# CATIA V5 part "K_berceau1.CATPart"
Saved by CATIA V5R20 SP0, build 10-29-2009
Part number: berceau1
Bounding box of the stored display mesh (mm): x -13.994 to 13.994, y 95 to 105, z -10 to 63.99
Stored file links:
  G:\Khaled_CFAO_2011\SIL\SIL_GR2\mdupuis\Khaled\CAD_ThinkMOTION\K_berceau1.CATPart
  G:\Dupuis_Maxime_Thinkmotion_CFAO\assemblage.CATProduct
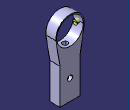
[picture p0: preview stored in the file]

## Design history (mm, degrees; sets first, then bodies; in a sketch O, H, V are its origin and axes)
External parameters (linked from other documents)
  External.diametrelunette = 20 mm
Set1
  Plane1 to Plane3: linked copy from another document
  Point1: linked copy from another document
  Line1: linked copy from another document
  Point2: linked copy from another document
Body1 (main body)
  Sketch1 on Plane3, origin (0, 100, 0), H (-1, 0, 0), V (0, 0, 1)
    point P1 (10, -10)
    line L1 (10, -10) -> (10, 25)
    point P2 (10, 25)
    line L2 (10, 25) -> (13.9237, 48.5401)
    point P3 (13.9237, 48.5401)
    point P4 (0, 50)
    line L3 (10, -10) -> (0, -10)
    point P5 (0, -10)
    reference projected point E1 (0, 50) from Point1
    point P6 (0, 36)
    reference intersected line E2 through (0, 0) direction (0, -1) from Plane2
    point P9 (0, -10)
    point P10 (-10, -10)
    line L4 (-10, -10) -> (0, -10)
    point P11 (-10, 25)
    line L5 (-10, -10) -> (-10, 25)
    point P12 (-13.9237, 48.5401)
    line L6 (-10, 25) -> (-13.9237, 48.5401)
    point P13 (0, 36)
    circle A1 centre (0, 10) radius 2.5
    point P14 (0, 10)
    arc A2 centre (0, 50) radius 14 from (13.9237, 48.5401) to (-13.9237, 48.5401) ccw
    circle A3 centre (0, 50) radius 13
    length L1 = 35
    length L3 = 10
    distance L3 H = 10
    radius A1 = 2.5
    radius A2 = 14 {= External.diametrelunette /2 + 4mm}
    radius A3 = 13 {= External.diametrelunette /2+3mm}
    vertical: L1 V
    coincidence: P4 V, P4 E1, P6 V, P5 P9, P6 P13, P14 E2
    horizontal: L3 H
    symmetry: P5 P9 E2, P1 P10 E2, L3 L4 E2, P2 P11 E2, L1 L5 E2, P3 P12 E2, L2 L6 E2, P6 P13 E2
  Pad1: profile Sketch1, direction (0, -1, 0), length 5, mirrored extent
  Sketch2 on face of Pad1 from Sketch1.L4, origin (0.8383, 99.4115, -10), H (1, 0, 0), V (0, -1, 0)
    point P1 (-0.8383, -0.5885)
    reference projected point E3 (-0.8383, -0.5885) from Point2
    coincidence: P1 E3
  Hole1: placed by Sketch2, at (0, 100, -10) direction (0, 0, 1), diameter 5, depth 48, threaded, thread diameter 6, thread depth 47, pitch 1
  Extract1: ExtractElem Body2
Body2
  Solid1: solid without history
